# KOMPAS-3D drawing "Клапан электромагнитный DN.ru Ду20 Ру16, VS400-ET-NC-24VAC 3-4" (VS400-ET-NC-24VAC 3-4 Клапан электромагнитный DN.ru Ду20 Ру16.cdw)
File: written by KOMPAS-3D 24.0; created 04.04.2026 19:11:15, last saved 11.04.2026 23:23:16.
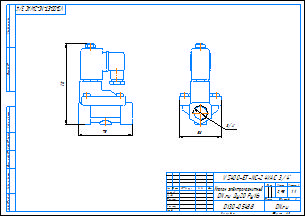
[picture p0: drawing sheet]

Document properties: c3d_UniqueCompID: ef56311e-7521-43dc-8291-0e6108b3d81d; Обозначение: VS400-ET-NC-220VAC 1-2; Наименование: Клапан электромагнитный DN.ru Ду15 Ру16; Автор: artio; Класс точности: c; Знак неуказанной шероховатости: Шероховатость не задана; Рассекать на разрезах: Да; c3d_UniqueCompID: ef56311e-7521-43dc-8291-0e6108b3d81d; Обозначение: VS400-ET-NC-220VAC 3-4; Наименование: Клапан электромагнитный DN.ru Ду20 Ру16; Автор: artio; Класс точности: c; Знак неуказанной шероховатости: Шероховатость не задана; Рассекать на разрезах: Да; c3d_UniqueCompID: ef56311e-7521-43dc-8291-0e6108b3d81d; Обозначение: VS400-ET-NC-220VAC 3-8; Наименование: Клапан электромагнитный DN.ru Ду10 Ру16; Автор: artio; Класс точности: c; Знак неуказанной шероховатости: Шероховатость не задана; Рассекать на разрезах: Да; Автор: artio; Форматы листов документа: A3; Полное имя файла: VS400-ET-NC-24VAC 3-4 Клапан электромагнитный DN.ru Ду20 Ру16.m3d; Масса: 0.954; Наименование: Клапан электромагнитный DN.ru Ду20 Ру16; Количество листов документа: 1; Примечание: D130-05488

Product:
- Body: Тело 1  | qty 1
    Масса: 1.210539
- Part/product: Клапан электромагнитный DN.ru Ду20 Ру16  | designation VS400-ET-NC-24VAC 3-4
    Масса: 0.954
    Раздел спецификации: Прочие изделия
    Примечание: D130-05488
    additional columns: ef56311e-7521-43dc-8291-0e6108b3d81d; VS400-ET-NC-220VAC 3-4; artio; c; Шероховатость не задана; Да

Views: Вид 1, Спереди, Проекционный вид 2
Referenced files in C:\Users\artio\OneDrive\Рабочий стол\Клапан электромагнитный DN.ru\VS400-ET-NC\VS400-ET-NC-24VDC\: VS400-ET-NC-24VDC 3-8 Клапан электромагнитный DN.ru Ду10 Ру16.m3d
Referenced files in C:\Users\artio\OneDrive\Рабочий стол\Клапан электромагнитный DN.ru\VS400-ET-NC\VS400-ET-NC-24VAC\: VS400-ET-NC-24VAC 3-4 Клапан электромагнитный DN.ru Ду20 Ру16.m3d
Referenced files in C:\Users\artio\OneDrive\Рабочий стол\Клапан электромагнитный DN.ru\VS400-ET-NC\: VS400-ET-NC-24VDC 3-8 Клапан электромагнитный DN.ru Ду10 Ру16.cdw
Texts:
  VS400-ET-NC-24VAC 3-4
  Клапан электромагнитный
  DN.ru Ду20 Ру16
  VS400-ET-NC-24VAC 3/4"
  VS400-ET-NC-24VAC 3/4"-
  Клапан электромагнитный DN.ru Ду20 Ру16
  VS400-ET-NC-24VAC 3-4 Клапан электромагнитный DN.ru Ду20 Ру16
Dimensions and other numbers on the sheet: 0; 3; 2; 4; 58; 3/4"; 75; 112; 1:1; 1; 0,95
